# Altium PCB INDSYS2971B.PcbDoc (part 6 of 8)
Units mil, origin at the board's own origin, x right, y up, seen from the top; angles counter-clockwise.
Board outline 6450 x 5820 mil, 6 copper layers (Top Layer, Int1 (PGND), Int2 (AGND), Int3 (Signal), Int4 (PGND), Bottom Layer), stack 70.536 mil thick; 787 components, 431 nets, 2530 pads, 2497 vias.
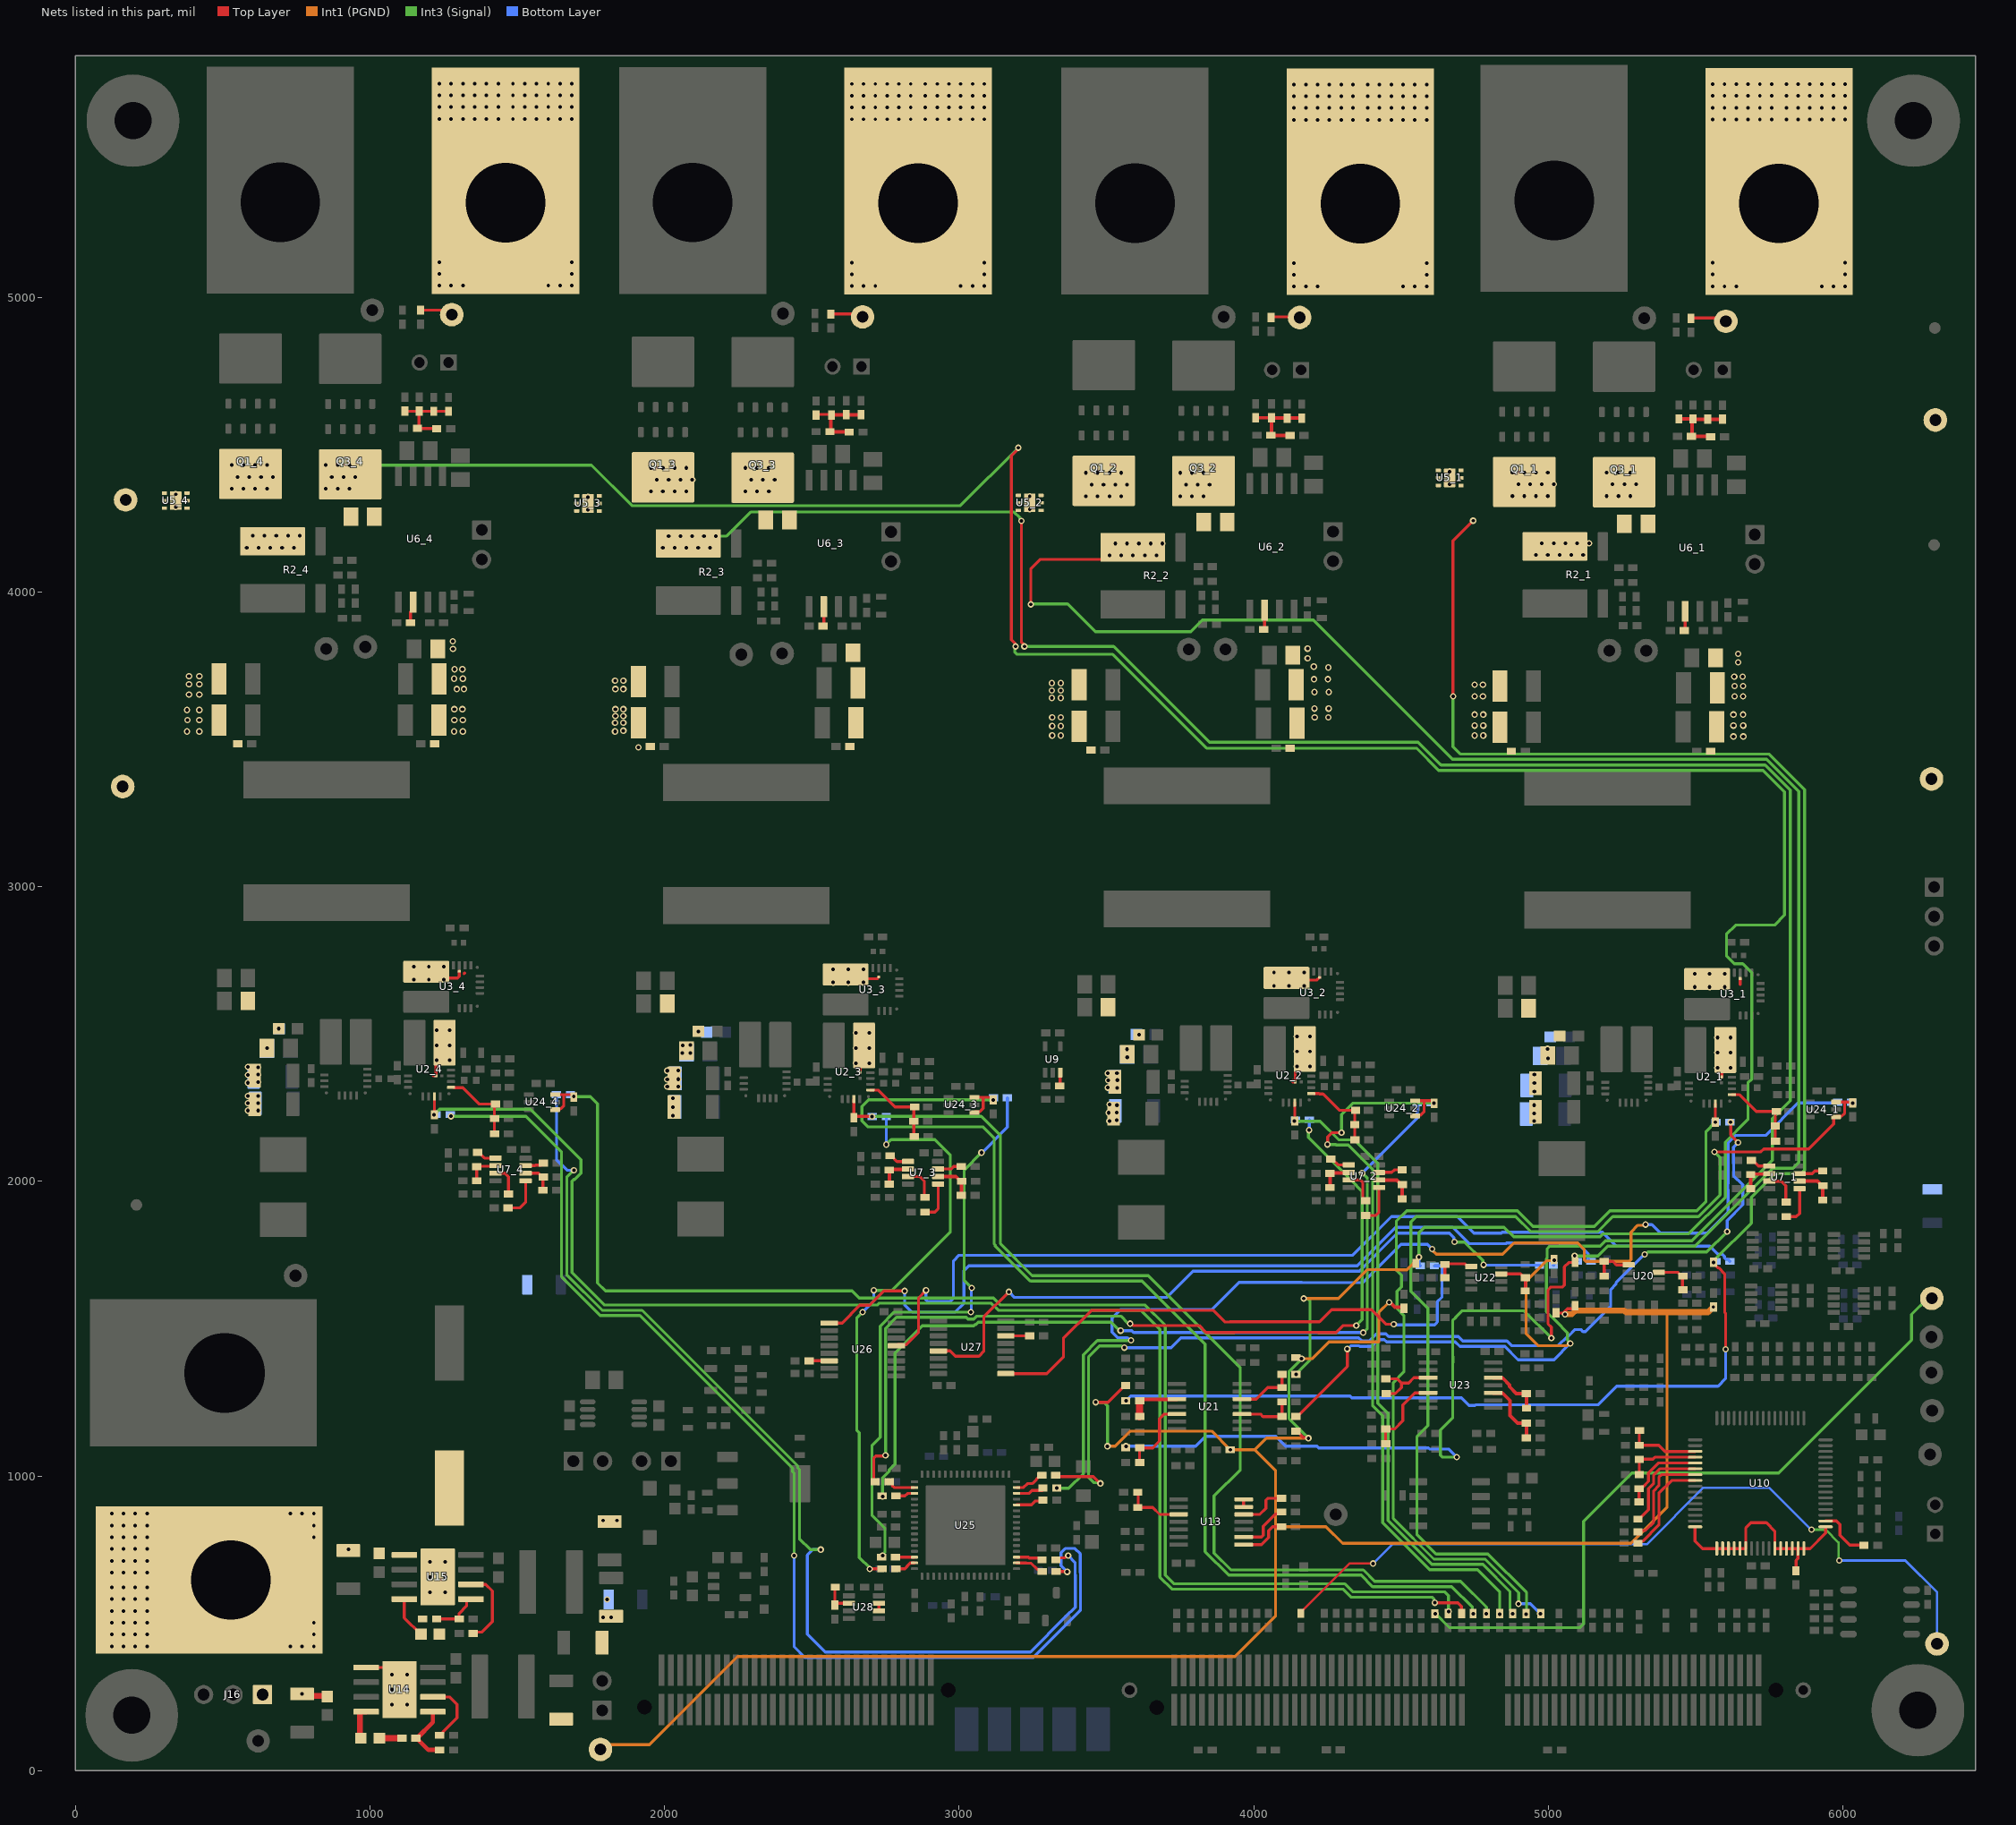
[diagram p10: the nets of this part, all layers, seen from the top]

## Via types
v1: diameter 22, hole 12.5, Top Layer to Bottom Layer, 873 vias
v2: diameter 22, hole 12, Top Layer to Bottom Layer, tented both sides, 788 vias
v3: diameter 22, hole 12, Top Layer to Bottom Layer, 586 vias
v4: diameter 22, hole 12.5, Top Layer to Bottom Layer, tented both sides, 249 vias
v5: diameter 24, hole 12, Top Layer to Bottom Layer, tented both sides, 1 vias

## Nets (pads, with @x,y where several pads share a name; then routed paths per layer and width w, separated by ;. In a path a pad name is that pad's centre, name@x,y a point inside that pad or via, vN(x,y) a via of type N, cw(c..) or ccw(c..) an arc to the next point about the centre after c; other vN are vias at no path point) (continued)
NetR17_1_1: R17_1.1 R18_1.2 R20_1.1 R21_1.2 R25_1.2 R28_1.2 | length 275.9
  Top Layer w12: R20_1.1@5443.39,4587.91 R17_1.1@5493.39,4587.91 ; R28_1.2@5551.1,4527.42 5550.37,4528.15 5486.59,4528.15 R25_1.2@5485.87,4528.88 5488.56,4531.57 5488.56,4584.05 5491.26,4586.75 R21_1.2@5541.26,4586.75 R18_1.2@5591.26,4586.75
NetR17_2_1: R17_2.1 R18_2.2 R20_2.1 R21_2.2 R25_2.2 R28_2.2 | length 275.9
  Top Layer w12: R20_2.1@4010.56,4591.91 R17_2.1@4060.56,4591.91 ; R28_2.2@4123.1,4531.42 4122.37,4532.15 4058.59,4532.15 R25_2.2@4057.87,4532.88 4060.56,4535.57 4060.56,4588.05 4063.26,4590.75 R21_2.2@4113.26,4590.75 R18_2.2@4163.26,4590.75
NetR17_3_1: R17_3.1 R18_3.2 R20_3.1 R21_3.2 R25_3.2 R28_3.2 | length 277.5
  Top Layer w10: R20_3.1@2514.01,4603.52 2560.1,4603.52 R17_3.1@2563.95,4599.66
  Top Layer w12: R28_3.2@2626.49,4543.03 2625.76,4543.76 2561.99,4543.76 R25_3.2@2561.26,4544.48 2563.95,4547.18 2563.95,4599.66 2566.15,4601.86 2566.65,4602.36 R21_3.2@2616.65,4602.36 R18_3.2@2666.65,4602.36
NetR17_4_1: R17_4.1 R18_4.2 R20_4.1 R21_4.2 R25_4.2 R28_4.2 | length 275.9
  Top Layer w10: R20_4.1@1116.26,4613.69 R17_4.1@1166.26,4613.69 ; R28_4.2@1226.1,4554.36 1225.37,4555.09 1161.59,4555.09 R25_4.2@1160.87,4555.81 1166.26,4561.21 R17_4.1@1166.26,4613.69 ; R18_4.2@1266.26,4613.69 R21_4.2@1216.26,4613.69 R17_4.1@1166.26,4613.69
NetR24_1_2: R24_1.2 U7_1.3 | length 82.4
  Top Layer w10: U7_1.3@5853.16,2026.44 5896.45,2026.44 5905.15,2035.14 R24_1.2@5931.98,2035.14
NetR24_2_2: R24_2.2 U7_2.3 | length 82.4
  Top Layer w10: U7_2.3@4425.16,2030.44 4468.45,2030.44 4477.15,2039.14 R24_2.2@4503.98,2039.14
NetR24_3_2: R24_3.2 U7_3.3 | length 82.4
  Top Layer w10: U7_3.3@2928.56,2042.05 2971.84,2042.05 2980.54,2050.75 R24_3.2@3007.37,2050.75
NetR24_4_2: R24_4.2 U7_4.3 | length 63.4
  Top Layer w10: U7_4.3@1528.16,2053.38 1560.36,2053.38 1562.06,2055.08 1581.22,2055.08 R24_4.2@1588.03,2061.89
NetR26_1_2: R26_1.2 U7_1.1 | length 133.5
  Top Layer w10: R26_1.2@5808.27,1880.14 5842.05,1880.14 5853.19,1891.29 U7_1.1@5853.16,1975.26
NetR26_2_2: R26_2.2 U7_2.1 | length 133.5
  Top Layer w10: R26_2.2@4380.27,1884.14 4414.05,1884.14 4425.19,1895.29 U7_2.1@4425.16,1979.26
NetR26_3_2: R26_3.2 U7_3.1 | length 133.5
  Top Layer w10: R26_3.2@2883.66,1895.75 2917.44,1895.75 2928.58,1906.89 U7_3.1@2928.56,1990.87
NetR26_4_2: R26_4.2 U7_4.1 | length 140.3
  Top Layer w10: R26_4.2@1468.62,1910.14 1508.9,1910.14 1528.16,1929.41 U7_4.1@1528.16,2002.2
NetR27_1_2: R27_1.2 R29_1.2 U7_1.2 | length 135.1
  Top Layer w12: U7_1.2@5853.16,2000.85 5913.35,2000.85 5929.05,1985.14 R27_1.2@5932.99,1985.14 5932.49,1984.64 5932.49,1937.26 R29_1.2@5931.98,1936.76
NetR27_2_2: R27_2.2 R29_2.2 U7_2.2 | length 135.1
  Top Layer w12: U7_2.2@4425.16,2004.85 4485.35,2004.85 4501.05,1989.14 R27_2.2@4504.99,1989.14 4504.49,1988.64 4504.49,1941.26 R29_2.2@4503.98,1940.76
NetR27_3_2: R27_3.2 R29_3.2 U7_3.2 | length 135.1
  Top Layer w12: U7_3.2@2928.56,2016.46 2988.74,2016.46 3004.44,2000.75 R27_3.2@3008.38,2000.75 3007.88,2000.25 3007.88,1952.87 R29_3.2@3007.37,1952.37
NetR27_4_2: R27_4.2 R29_4.2 U7_4.2 | length 110.8
  Top Layer w10: U7_4.2@1528.16,2027.79 1571.45,2027.79 1584.09,2015.14 R27_4.2@1588.03,2015.14 1586.38,2013.49 R29_4.2@1586.38,1970.14
NetR30_1_2: R30_1.2 U6_1.2 | length 66.6
  Top Layer w10: R30_1.2@5462.24,3869.5 5465,3872.26 U6_1.2@5465,3934.94
NetR30_2_2: R30_2.2 U6_2.2 | length 66.6
  Top Layer w10: R30_2.2@4034.24,3873.5 4037,3876.26 U6_2.2@4037,3938.94
NetR30_3_2: R30_3.2 U6_3.2 | length 66.6
  Top Layer w10: R30_3.2@2537.64,3885.11 2540.39,3887.87 U6_3.2@2540.39,3950.55
NetR30_4_2: R30_4.2 U6_4.2 | length 73.1
  Top Layer w10: R30_4.2@1137.24,3896.44 1137.24,3933.37 1146.1,3942.22 U6_4.2@1146.1,3965.85
NetR32_1_2: R32_1.2 U7_1.5 | length 68.8
  Top Layer w10: R32_1.2@5690.05,2071.44 5693.99,2071.44 5713.4,2052.03 U7_1.5@5750.8,2052.03
NetR32_2_2: R32_2.2 U7_2.5 | length 68.8
  Top Layer w10: R32_2.2@4262.05,2075.44 4265.99,2075.44 4285.4,2056.03 U7_2.5@4322.8,2056.03
NetR32_3_2: R32_3.2 U7_3.5 | length 68.8
  Top Layer w10: R32_3.2@2765.45,2087.05 2769.38,2087.05 2788.79,2067.64 U7_3.5@2826.19,2067.64
NetR32_4_2: R32_4.2 U7_4.5 | length 68.8
  Top Layer w10: R32_4.2@1365.05,2098.38 1368.99,2098.38 1388.4,2078.97 U7_4.5@1425.8,2078.97
NetR33_1_2: R33_1.2 U7_1.7 | length 117.9
  Top Layer w10: U7_1.7@5750.8,2000.85 5790.65,2000.85 5806.35,1985.14 5806.35,1932.06 R33_1.2@5808.27,1930.14
NetR33_2_2: R33_2.2 U7_2.7 | length 119.9
  Top Layer w10: U7_2.7@4322.8,2004.85 4362.65,2004.85 4370,1997.5 4370,1940.96 4376.81,1934.14 R33_2.2@4380.27,1934.14
NetR33_3_2: R33_3.2 U7_3.7 | length 117.9
  Top Layer w10: U7_3.7@2826.19,2016.46 2866.04,2016.46 2881.75,2000.75 2881.75,1947.67 R33_3.2@2883.66,1945.75
NetR33_4_2: R33_4.2 U7_4.7 | length 107.5
  Top Layer w10: U7_4.7@1425.8,2027.79 1457.73,2027.79 1469.48,2016.05 R33_4.2@1469.48,1957.08
NetR34_1_2: R34_1.2 R35_1.2 U7_1.6 | length 112.6
  Top Layer w12: R35_1.2@5687.2,1975.38 R34_1.2@5687.2,2022.99 5688.93,2024.72 5749.08,2024.72 U7_1.6@5750.8,2026.44
NetR34_2_2: R34_2.2 R35_2.2 U7_2.6 | length 112.6
  Top Layer w12: R35_2.2@4259.2,1979.38 R34_2.2@4259.2,2026.99 4260.93,2028.72 4321.08,2028.72 U7_2.6@4322.8,2030.44
NetR34_3_2: R34_3.2 R35_3.2 U7_3.6 | length 112.6
  Top Layer w12: R35_3.2@2762.59,1990.99 R34_3.2@2762.59,2038.6 2764.32,2040.33 2824.47,2040.33 U7_3.6@2826.19,2042.05
NetR34_4_2: R34_4.2 R35_4.2 U7_4.6 | length 112.5
  Top Layer w10: R35_4.2@1362.2,2002.32 1362.2,2049.72 1364.14,2051.66 1424.08,2051.66 U7_4.6@1425.8,2053.38
NetR77_2: R77.2 U9.3 | length 46.5
  Top Layer w10: R77.2@3341.12,2323.72 3343.09,2325.69 U9.3@3343.09,2369.43
NetR79_1: R79.1 U10.6 | length 323.5
  Top Layer w10: R79.1@5304.57,853.61 5308.5,853.61 5340,885.11 5340,956.69 5357.87,974.56 5357.87,1003.38 5378.85,1024.36 U10.6@5498.54,1024.36
NetR80_1: R80.1 U10.8 | length 345.6
  Top Layer w10: R80.1@5304.57,771.33 5311.38,778.14 5319.79,778.14 5375.58,833.93 5375.58,836.12 5375.75,836.29 5375.75,941.88 5418.78,984.91 5478.94,984.91 5479.02,984.99 U10.8@5498.54,984.99
NetR82_1: R82.1 U10.7 | length 353.1
  Top Layer w10: R82.1@5304.57,810.7 5308.8,814.93 5329.11,814.93 5357.87,843.69 5357.87,949.28 5375.75,967.16 5375.75,995.97 5384.37,1004.59 5498.46,1004.59 U10.7@5498.54,1004.67
NetR99_2: R99.2 U10.34 | length 185.3
  Top Layer w10: U10.34@5941.46,847.19 5977.95,847.19 5990,835.14 5990,798.65 6023.5,765.14 R99.2@6071.38,765.14
NetR101_2: R101.2 U10.16 U10.17 U10.18 U10.19 U10.20 U10.21 U10.22 U10.27 U10.28 U10.29 U10.30 U10.31 U10.32 U10.33 | length 772.2
  Top Layer w10: U10.16@5498.54,827.51 5498.54,779.08 5523.94,753.69 U10.17@5572.36,753.69 U10.18@5592.05,753.69 U10.19@5611.73,753.69 U10.20@5631.42,753.69 U10.21@5651.1,753.69 U10.22@5670.79,753.69 5670.79,824.32 5687.84,841.37 5740.69,841.37 5769.21,812.85 U10.27@5769.21,753.69 U10.28@5788.9,753.69 U10.29@5808.58,753.69 U10.30@5828.27,753.69 U10.31@5847.95,753.69 ; R101.2@5841.02,678.18 5841.02,713.22 5847.87,720.07 5847.87,753.61 U10.31@5847.95,753.69 ; U10.33@5941.46,827.51 5941.46,805.85 5889.29,753.69 U10.32@5867.64,753.69 U10.31@5847.95,753.69
NetR111_1: R111.1 U13.8 | length 167.5
  Top Layer w10: U13.8@3965.94,767.25 4026.47,767.25 4050.51,791.29 4050.51,814.77 4063.66,827.92 R111.1@4094.61,827.92
NetR112_1: R112.1 R114.1 U13.3 | length 192.2
  Top Layer w10: R114.1@3606.06,893.35 R114.1@3611.06,893.35 ; R112.1@3606.06,944.53 3607.87,942.72 3607.87,896.54 3608.56,895.85 R114.1@3611.06,893.35 ; U13.3@3735,870.14 3734.46,869.61 3680.71,869.61 3656.97,893.35 R114.1@3611.06,893.35
NetR113_2: R113.2 U13.9 | length 181.9
  Top Layer w10: U13.9@3965.94,792.84 4026.78,792.84 4032.64,798.69 4032.64,829.17 4074.85,871.38 4087.8,871.38 R113.2@4094.61,878.19
NetR117_1: R117.1 U13.12 | length 167.5
  Top Layer w10: U13.12@3965.94,869.61 4020.75,869.61 4041.49,890.35 4041.49,918.16 4047.35,924.02 R117.1@4094.61,924.02
NetR118_1: R118.1 R122.2 U14.5 | length 210.8
  Top Layer w15: R122.2@1155.12,110.14 R122.2@1159.06,110.14 ; U14.5@1213.19,200.1 1213.19,164.28 R122.2@1159.06,110.14 ; R118.1@1236.38,70.14 1198.13,70.14 1163.37,104.91 1163.37,105.83 R122.2@1159.06,110.14
NetR119_1: R119.1 R123.2 U15.5 | length 169.5
  Top Layer w10: R123.2@1225.87,514.74 R119.1@1302.19,514.74 1305.75,518.29 1305.44,518.29 1302.19,521.55 1302.19,533.4 1327.68,558.89 1327.68,577.23 1332.52,582.07 U15.5@1342.7,582.07
NetR120_1: R120.1 U14.6 | length 223.4
  Top Layer w10: U14.6@1213.19,250.1 1269.43,250.1 1295,224.54 1295,178.77 1247.13,130.89 1247.13,126.96 1240.32,120.14 R120.1@1236.38,120.14
NetR121_1: R121.1 U15.6 | length 270.3
  Top Layer w10: U15.6@1342.7,632.07 1393.02,632.07 1415.28,609.82 1415.28,505.27 1380.18,470.18 1358.06,470.18 1351.28,463.4 R121.1@1349.43,465.25
NetR124_2: R124.2 U14.4 | length 113.2
  Top Layer w20: R124.2@968.5,110.14 965.16,113.49 965.16,199.95 965,199.95 965.16,200.1 U14.4@986.81,200.1
NetR125_2: R125.2 U15.4 | length 142.5
  Top Layer w10: U15.4@1116.32,582.07 1116.32,518.52 1171.44,463.4 R125.2@1172.42,463.4
NetR134_1: R134.1 R135.2 U20.3 | length 134.2
  Top Layer w10: U20.3@5375.58,1691.23 5440.7,1691.23 5455.15,1676.78 R134.1@5455.92,1676.78 ; R135.2@5457.3,1631.78 5455.92,1633.16 R134.1@5455.92,1676.78 ; R134.1@5457.44,1678.44 5455.92,1676.92 R134.1@5455.92,1676.78
NetR137_1: R137.1 R140.2 U21.3 | length 182.9
  Top Layer w12: R140.2@3612.56,1255.52 3617.26,1260.22 3738.6,1260.22 U21.3@3739.49,1261.11
  Top Layer w25: R137.1@3612.56,1201.83 R140.2@3612.56,1255.52
NetR145_1: R145.1 R146.2 U20.5 | length 133.6
  Top Layer w10: R145.1@5189.68,1728.44 R146.2@5189.68,1678.44 5189.68,1678.02 R146.2@5190.92,1676.78 ; R145.1@5196.27,1727.78 5220.43,1727.78 5231.39,1716.82 U20.5@5273.21,1716.82
NetR148_1: R148.1 R152.2 U21.5 | length 268.1
  Top Layer w10: R148.1@3612.56,1045.52 R152.2@3612.56,1095.52 3656.79,1095.52 3680,1118.73 3680,1193.47 3696.46,1209.93 U21.5@3739.49,1209.93
NetR156_1: R156.1 R157.2 U22.3 | length 135.4
  Top Layer w10: U22.3@4840.54,1685.76 4905.39,1685.76 4920.43,1670.72 4920.43,1668.12 4922.12,1668.12 4922.12,1631.43 4923.61,1629.93 4925.43,1628.12 R157.2@4921.8,1628.12
NetR158_1: R158.1 R160.2 U21.10 | length 189.5
  Top Layer w10: U21.10@3959.96,1209.93 4023.35,1209.93 4031.46,1201.83 R160.2@4096.1,1201.83 R158.1@4096.1,1251.83
NetR167_1: R167.1 R169.2 U21.12 | length 193.2
  Top Layer w10: U21.12@3959.96,1261.11 4007.96,1261.11 4046.99,1300.14 R167.1@4096.38,1300.14 4096.38,1338.77 R169.2@4095,1340.14
NetR168_1: R168.1 R170.2 U22.5 | length 137.7
  Top Layer w10: R170.2@4649.05,1673.12 4650.43,1673.12 4649.74,1673.81 4649.05,1674.5 R168.1@4649.05,1718.12 ; R168.1@4651.04,1720.11 4717.61,1720.11 4726.37,1711.35 U22.5@4738.18,1711.35
NetR177_1: R177.1 R179.2 U23.5 | length 276.8
  Top Layer w10: R177.1@4448.07,1109.72 R179.2@4448.07,1159.72 4478.82,1159.72 4506.38,1187.28 4506.38,1241.41 4547.4,1282.43 U23.5@4592.31,1282.43
NetR178_1: R178.1 R180.2 U23.3 | length 232.8
  Top Layer w10: R180.2@4448.07,1329.72 4487.44,1329.72 4501.38,1315.78 ; R178.1@4450,1279.72 4480.75,1279.72 4501.38,1300.35 4501.38,1315.78 ; U23.3@4592.31,1333.61 4543.46,1333.61 4525.63,1315.78 4501.38,1315.78
NetR185_1: R185.1 R187.2 U23.10 | length 235.5
  Top Layer w12: U23.10@4812.79,1282.43 4813.68,1281.54 4844.92,1281.54 4870.24,1256.22 4870.24,1205.04 4895.56,1179.72 R185.1@4925.71,1179.72 R187.2@4925.71,1129.72
NetR186_1: R186.1 R188.2 U23.12 | length 188.5
  Top Layer w12: U23.12@4812.79,1333.61 4813.68,1332.72 4844.92,1332.72 4868.44,1309.2 4868.44,1303.24 4891.96,1279.72 R188.2@4925.71,1279.72 4926.04,1279.38 4926.04,1230.37 R186.1@4926.21,1230.21
NetR208_1: R208.1 U25.46 | length 90.6
  Top Layer w10: U25.46@3194.76,941.2 3237.7,941.2 3246.95,950.45 R208.1@3281.52,950.45
NetR209_1: R209.1 U25.47 | length 102.3
  Top Layer w10: U25.47@3194.76,960.88 3218.61,960.88 3231.85,974.13 3248.03,974.13 3276.06,1002.16 R209.1@3280,1002.16
NetR217_1: R217.1 U25.3 | length 66.4
  Top Layer w10: R217.1@2785.31,932.87 2816.06,932.87 2824.11,940.92 2848.03,940.92 U25.3@2848.31,941.2
NetR219_1: R219.1 U25.2 | length 98.9
  Top Layer w10: R219.1@2761.97,980.57 2765.91,980.57 2772.72,973.76 2772.72,966.74 2778.57,960.88 2807.68,960.88 2808.04,960.53 2827.82,960.53 2828.17,960.88 U25.2@2848.31,960.88
NetR226_1: R226.1 U25.14 | length 64.1
  Top Layer w10: R226.1@2784.18,724.66 U25.14@2848.31,724.66
NetR229_1: R229.1 U25.15 | length 71.9
  Top Layer w10: R229.1@2785.31,685.29 2816.06,685.29 2823.62,692.86 2823.62,694.19 2834.14,704.7 2848.03,704.7 U25.15@2848.31,704.98
NetR232_2: R232.2 U25.44 | length 90.4
  Top Layer w10: U25.44@3194.76,901.83 3245.71,901.83 3259.24,915.35 R232.2@3279.57,915.35
NetR233_1: R233.1 U25.35 | length 90.1
  Top Layer w10: U25.35@3194.76,724.66 3234.63,724.66 3237.4,721.89 3274.67,721.89 R233.1@3281.09,715.48
NetR234_1: R234.1 U25.34 | length 99.5
  Top Layer w10: U25.34@3194.76,704.98 3228.17,704.98 3229.13,704.02 3243.72,704.02 3264.78,682.96 3275.5,682.96 R234.1@3282.31,676.14
NetR236_2: R236.2 U26.13 | length 3272.3
  Top Layer w10: U26.13@2786.82,1442.18 2790.68,1446.04 2820.54,1446.04 2861.97,1487.47 2861.97,1604.54 v2(2887.36,1629.93)
  Bottom Layer w10: v2(2887.36,1629.93) 2887.36,1597.88 2893.22,1592.02 2969.35,1592.02 2980.59,1603.26 2980.59,1730.4 2999.33,1749.14 4336.52,1749.14 4467.53,1880.14 4691.68,1880.14 4747.81,1824.01 4840.72,1824.01 4843.59,1826.88 5184.05,1826.88 5230.79,1780.14 5548.41,1780.14 5575.43,1753.12 5590.5,1753.12 5598.04,1745.58 5598.04,1741.11 5603.9,1735.25 5609.85,1735.25 R236.2@5616.66,1728.44
NetR238_2: R238.2 U26.1 | length 2937
  Top Layer w10: U26.1@2558.48,1518.95 2603.01,1518.95 2632.73,1548.68 2632.73,1550.42 2662.45,1580.14 2696.32,1580.14 2744.42,1628.24 v2(2815.19,1628.24)
  Bottom Layer w10: v2(2815.19,1628.24) 2815.19,1580.08 2839,1556.27 2986.55,1556.27 3016.34,1586.06 3016.34,1697.22 3032.51,1713.39 4351.33,1713.39 4482.33,1844.4 4676.87,1844.4 4733.01,1788.26 4855.53,1788.26 4858.4,1791.14 5036.88,1791.14 5041.72,1786.29 5103.12,1786.29 5136.1,1753.32 5136.1,1735.25 5142.91,1728.44 R238.2@5145.7,1728.44
NetR243_2: R243.2 U26.6 | length 68.4
  Top Layer w10: R243.2@2490.11,1391 U26.6@2558.48,1391
NetR245_2: R245.2 U27.13 | length 2365.2
  Top Layer w10: U27.13@2929.76,1424.35 2969.45,1424.35 2987.67,1406.13 3067.14,1406.13 3083.62,1422.61 3083.62,1539.74 v2(3168.9,1625.02)
  Int3 (Signal) w10: v2(4681.47,1794.26) 4715.12,1794.26 4778.14,1731.23 4778.14,1719.03 v2(4780.43,1716.75)
  Bottom Layer w10: v2(3168.9,1625.02) 3187.71,1606.21 3704.8,1606.21 3794.11,1695.52 4358.73,1695.52 4487.27,1824.06 4664.39,1824.06 4679.18,1809.27 4679.18,1796.56 v2(4681.47,1794.26) ; v2(4780.43,1716.75) 4781.39,1715.78 4969.3,1715.78 R245.2@4970.27,1714.82
NetR247_2: R247.2 U27.1 | length 1871.1
  Top Layer w10: U27.1@3158.11,1347.58 3272.71,1347.58 3297.54,1347.58 3324.54,1374.58 3325.17,1374.58 3351.97,1401.38 3351.97,1402.01 3353.81,1403.85 3353.81,1467.34 3448.47,1562 3863.44,1562 3902.75,1522.69 3918.85,1522.69 3919.85,1523.69 4223.28,1523.69 4261.58,1562 4262.31,1562 4264.98,1564.66 4399.85,1564.66 4449.49,1515.02 v2(4475.61,1515.02)
  Bottom Layer w10: v2(4475.61,1515.02) 4477.91,1512.72 4614.01,1512.72 4619.87,1518.58 4619.87,1519.52 4623.36,1523.01 4623.36,1591.2 4639.21,1607.04 4639.21,1707.54 4633.35,1713.4 R247.2@4613.23,1713.4
NetR250_2: R250.2 R251.1 U28.2 | length 111.7
  Top Layer w10: R251.1@2579.44,622.93 2578.07,621.56 R250.2@2578.07,561.56 2584.33,567.82 U28.2@2625.23,567.82
NetR254_2: R254.2 U27.6 | length 80.8
  Top Layer w10: U27.6@3158.11,1475.53 R254.2@3238.94,1475.53
NetTP18_1: R71.2 TP18.1 | length 2695.3
  Top Layer w8: R71.2@4160,533.77 4160,537.7 4325.19,702.89 v2(4405,702.89)
  Int3 (Signal) w8: v2(5893.46,817.94) 5942.06,817.94 5985.66,774.34 5985.66,715.84 v2(5988.34,713.16)
  Bottom Layer w8: v2(4405,702.89) 4470.55,768.45 5334.26,768.45 5525.96,960.14 5750,960.14 5892.2,817.94 v2(5893.46,817.94) ; v2(5988.34,713.16) 6212.07,713.16 6320,605.23 TP18.1@6320,430.14
NetTP19_1: R54.2 TP19.1 | length 2425
  Top Layer w10: R54.2@4614.73,532.28 4615.39,532.95 v2(4617.06,532.95)
  Int3 (Signal) w10: v2(4617.06,532.95) 4664.97,485.04 5106.55,485.04 5120,498.49 5120,845.74 5284.38,1010.12 5782,1010.12 6233.6,1461.72 6233.6,1548.6 6288.02,1603.02 TP19.1@6302.24,1603.02
NetU13_13: U13.13 U13.14 | length 25.6
  Top Layer w10: U13.13@3965.94,895.2 U13.14@3965.94,920.79
NetU28_6: U28.6 U28.7 | length 25.6
  Top Layer w10: U28.6@2727.59,542.23 U28.7@2727.59,567.82
OS0: R105.1 R110.2 U10.3 | length 248.4
  Top Layer w10: R105.1@5309.76,1154.56 5309.17,1153.97 R110.2@5309.17,1104.56 5375,1104.56 5396.14,1083.41 U10.3@5498.54,1083.41
OS1: R104.1 R109.2 U10.4 | length 244.5
  Top Layer w10: R104.1@5309.17,1004.56 R109.2@5309.17,1056.76 5355,1056.76 5361.96,1063.73 U10.4@5498.54,1063.73
OS2: R103.1 R108.2 U10.5 | length 288.1
  Top Layer w10: R108.2@5308.43,911.8 R103.1@5308.43,956.69 5315.24,963.5 5321.53,963.5 5340,981.96 5340,1010.78 5373.26,1044.04 U10.5@5498.54,1044.04
OUTP1: Q1_1.5 Q1_1.6 Q1_1.7 Q1_1.8 Q1_1.9@4919,4373.95 Q3_1.5 Q3_1.6 Q3_1.7 Q3_1.8 Q3_1.9@5257.36,4372.95 R2_1.3 R6_1.2 R133.1 R140.1 R236.1 U5_1.4 U5_1.5 U5_1.6 | length 6340.6
  Top Layer w10: v2(4676.8,3646.14) 4676.8,4174.26 v2(4745,4242.46) ; v2(5560.92,1725.41) 5560.92,1721.47 5575.6,1706.78 5578.06,1706.78 5599.03,1685.82 5599.03,1556.16 5602.15,1553.04 v2(5602.15,1430.15)
  Int3 (Signal) w10: v2(4676.8,3646.14) 4676.8,3474.8 4701.13,3450.47 5749.12,3450.47 5870,3329.59 5870,2037.91 5858.53,2026.44 5770.23,2026.44 5689.74,1945.95 5689.74,1858.33 5566.92,1735.51 5566.92,1734.65 5560.92,1728.65 v2(5560.92,1725.41)
  Bottom Layer w10: v2(3566.14,1255.52) 3582.13,1271.51 4327.32,1271.51 4333.32,1265.51 4705,1265.51 4731.49,1239.03 4751.26,1239.03 4753.87,1241.64 5168.87,1241.64 5232.09,1304.85 5576.57,1304.85 5602.15,1330.44 v2(5602.15,1430.15)
  other v1: 4958.39,4126.14 4998.39,4126.14 5038.39,4126.14 5078.39,4126.14 5118.39,4126.14 4978.39,4166.14 5018.39,4166.14 5058.39,4166.14 5098.39,4166.14 5138.39,4166.14 4878.39,4326.14 4918.39,4326.14 4958.39,4326.14 4998.39,4326.14 5198.39,4326.14 5238.39,4326.14 5278.39,4326.14 4898.39,4366.14 4938.39,4366.14 4978.39,4366.14 5018.39,4366.14 5218.39,4366.14 5258.39,4366.14 5298.39,4366.14 4878.39,4406.14 4918.39,4406.14 4958.39,4406.14 4998.39,4406.14 5198.39,4406.14 5238.39,4406.14 5278.39,4406.14
OUTP2: Q1_2.5 Q1_2.6 Q1_2.7 Q1_2.8 Q1_2.9@3491,4377.95 Q3_2.5 Q3_2.6 Q3_2.7 Q3_2.8 Q3_2.9@3829.36,4376.95 R2_2.3 R6_2.2 R144.1 R152.1 R238.1 U5_2.4 U5_2.5 U5_2.6 | length 7929.6
  Top Layer w10: v2(3243.39,3958.4) 3243.39,4080.05 3274.32,4110.98 3495.83,4110.98 v1(3510,4125.14) ; v2(5010.51,1468.39) 5010.51,1505.15 4999.14,1516.52 4999.14,1631.69 5008.93,1641.49 5049.14,1641.49 5055,1647.35 5055,1709.73 5069.96,1724.69 R144.1@5090.2,1724.69 ; v2(5089.47,1747.03) 5090.19,1746.3 R144.1@5090.19,1726.13
  Int3 (Signal) w10: v2(3243.39,3958.4) 3245.14,3960.14 3367.94,3960.14 3462.56,3865.52 3786.12,3865.52 3825.51,3904.92 4202.55,3904.92 4674.88,3432.59 5741.72,3432.59 5850.62,3323.69 5850.62,2063.77 5831.17,2044.32 5762.83,2044.32 5498.66,1780.14 5201.46,1780.14 5168.34,1747.03 v2(5089.47,1747.03) ; v2(4689.35,1063.73) 4640.89,1063.73 4634.11,1070.5 4634.11,1155.42 4675.4,1196.71 4675.4,1383.54 4676.8,1384.94 4676.8,1404.72 4675.4,1406.11 4675.4,1527.35 4685.17,1537.12 4685.17,1538.53 4707.11,1560.46 4870.05,1560.46 4870.11,1560.52 4918.37,1560.52 v2(5010.51,1468.39)
  Bottom Layer w10: v2(3566.14,1101.14) 3803.59,1101.14 3836.84,1134.4 4074.94,1134.4 4108.19,1101.14 4214.47,1101.14 4220.47,1095.14 4240.25,1095.14 4593.08,1095.14 4596.82,1091.4 4661.68,1091.4 v2(4689.35,1063.73) ; v2(5089.47,1747.03) 5089.47,1735.25 5096.28,1728.44 R238.1@5098.46,1728.44
  other v1: 3550,4125.14 3590,4125.14 3630,4125.14 3670,4125.14 3530,4165.14 3570,4165.14 3610,4165.14 3650,4165.14 3690,4165.14 3430,4325.14 3470,4325.14 3510,4325.14 3550,4325.14 3750,4325.14 3790,4325.14 3830,4325.14 3450,4365.14 3490,4365.14 3530,4365.14 3570,4365.14 3770,4365.14 3810,4365.14 3850,4365.14 3430,4405.14 3470,4405.14 3510,4405.14 3550,4405.14 3750,4405.14 3790,4405.14 3830,4405.14
OUTP3: Q1_3.5 Q1_3.6 Q1_3.7 Q1_3.8 Q1_3.9@1994.39,4389.56 Q3_3.5 Q3_3.6 Q3_3.7 Q3_3.8 Q3_3.9@2332.75,4388.56 R2_3.3 R6_3.2 R155.1 R160.1 R245.1 U5_3.4 U5_3.5 U5_3.6 | length 8462.3
  Top Layer w10: v2(3211.53,4241.4) 3211.53,3829.38 3219.03,3821.88 3219.03,3817.99 v2(3221.33,3815.69) ; R160.1@4143.35,1201.83 4147.29,1201.83 4317.7,1372.24 v2(4317.7,1431.03)
  Int3 (Signal) w10: v1(2173.78,4190.14) 2210.39,4190.14 2292.22,4271.98 3186.91,4271.98 3206.12,4252.76 3206.12,4250.05 3209.67,4246.51 v2@3212.38,4246.51 ; v2(3221.33,3815.69) 3524.45,3815.69 3850,3490.14 4557.83,3490.14 4633.26,3414.72 4635.28,3414.72 4636.98,3413.02 5736.02,3413.02 5821.4,3327.63 5821.4,2274.06 5761.02,2213.68 5761.02,2071.4 5487.64,1798.02 5193.73,1798.02 5175.86,1780.14 5004.57,1780.14 4996.1,1771.68 4996.1,1739.5 4993.74,1737.14 4993.74,1676.06 4993.66,1675.98 4993.66,1650.08 4994.14,1649.59 4994.14,1623.69 4993.74,1623.29 4993.74,1557.45 5026.68,1524.51 5065.48,1485.71 5065.48,1461.86 5074.52,1452.82 v2(5074.52,1450)
  Int1 (PGND) w10: v2(5019.83,1732.99) 5017.53,1730.69 4993.77,1730.69 4925,1661.93 4925,1482.64 4965.12,1442.52 5063.8,1442.52 5071.28,1450 v2(5074.52,1450)
  Bottom Layer w10: v2(4317.7,1431.03) 4318.32,1431.03 4329.56,1442.27 4357.75,1442.27 4360.13,1439.9 4399.67,1439.9 4422.84,1463.07 4443.25,1463.07 4450.92,1455.4 4684.4,1455.4 4699.9,1439.9 4852.26,1439.9 4897.38,1394.77 5019.3,1394.77 v2(5074.52,1450) ; R245.1@5017.51,1714.82 5019.83,1717.13 v2(5019.83,1732.99)
  other v1: 1993.78,4150.14 2033.78,4150.14 2073.78,4150.14 2113.78,4150.14 2153.78,4150.14 2013.78,4190.14 2053.78,4190.14 2093.78,4190.14 2133.78,4190.14 1953.78,4341.75 1993.78,4341.75 2033.78,4341.75 2073.78,4341.75 2273.78,4341.75 2313.78,4341.75 2353.78,4341.75 1973.78,4381.75 2013.78,4381.75 2053.78,4381.75 2093.78,4381.75 2293.78,4381.75 2333.78,4381.75 2373.78,4381.75 1953.78,4421.75 1993.78,4421.75 2033.78,4421.75 2073.78,4421.75 2273.78,4421.75 2313.78,4421.75 2353.78,4421.75
OUTP4: Q1_4.5 Q1_4.6 Q1_4.7 Q1_4.8 Q1_4.9@594,4400.89 Q3_4.5 Q3_4.6 Q3_4.7 Q3_4.8 Q3_4.9@932.36,4399.89 R2_4.3 R6_4.2 R166.1 R169.1 R247.1 U5_4.4 U5_4.5 U5_4.6 | length 9544.1
  Top Layer w10: v2@3189.16,3826.05 3176.84,3838.37 3176.84,4462.66 3201.08,4486.9 v2(3201.08,4490.14) ; R166.1@4550.43,1721.74 4557.24,1728.56 4557.24,1735.9 4561.01,1739.67 v2(4561.01,1742.91)
  Int3 (Signal) w10: v1(929.77,4431.14) 1751.59,4431.14 1889.23,4293.5 3004.43,4293.5 v2(3201.08,4490.14) ; v2(3191.45,3815.69) 3189.16,3813.4 3189.16,3804.91 3188.84,3804.59 3188.84,3796.31 3196.34,3788.81 3521.34,3788.81 3840,3470.14 4552.55,3470.14 4627.55,3395.14 5728.61,3395.14 5802.2,3321.56 5802.2,2903.74 5768.46,2870 5635.77,2870 5605.06,2839.29 5605.06,2766.07 5632.06,2739.07 5660.12,2739.07 5690.65,2708.54 5690.65,2347.04 5677.94,2334.33 5677.94,2210.01 5601.28,2133.35 5601.28,1946.5 5476.87,1822.09 5186.45,1822.09 5176.09,1811.73 4882.47,1811.73 4849.81,1844.4 4579.6,1844.4 4561.01,1825.8 v2(4561.01,1742.91) ; v2(4143.62,1345.14) 4190.79,1392.31 4190.79,1594.83 4184.93,1600.69 4171.84,1600.69 v2(4170,1602.53)
  Int1 (PGND) w10: v2(4170,1602.53) 4287.49,1602.53 4385.36,1700.4 4482.6,1700.4 4483.1,1699.89 4519.89,1699.89 4561.01,1741.01 v2(4561.01,1742.91)
  Bottom Layer w10: v2(4561.01,1742.91) 4561.01,1718.37 R247.1@4565.99,1713.4
  other v1: 581.33,4151.14 621.33,4151.14 661.33,4151.14 701.33,4151.14 741.33,4151.14 601.33,4191.14 641.33,4191.14 681.33,4191.14 721.33,4191.14 761.33,4191.14 529.77,4351.14 569.77,4351.14 609.77,4351.14 649.77,4351.14 849.77,4351.14 889.77,4351.14 929.77,4351.14 549.77,4391.14 589.77,4391.14 629.77,4391.14 669.77,4391.14 869.77,4391.14 909.77,4391.14 949.77,4391.14 529.77,4431.14 569.77,4431.14 609.77,4431.14 649.77,4431.14 849.77,4431.14 889.77,4431.14
PGND: C1.2 C2_1.1 C2_2.1 C2_3.1 C2_4.1 C3_1.2 C3_2.2 C3_3.2 C3_4.2 C4_1.1 C4_2.1 C4_3.1 C4_4.1 C5_1.2 C5_2.2 C5_3.2 C5_4.2 C6_1.1 C6_2.1 C6_3.1 C6_4.1 C7_1.2 C7_2.2 C7_3.2 C7_4.2 C8_1.2 C8_2.2 C8_3.2 C8_4.2 C9_1.1 C9_2.1 C9_3.1 C9_4.1 C11_1.2 C11_2.2 C11_3.2 C11_4.2 C12_1.2 C12_2.2 C12_3.2 C12_4.2 C13_1.1 C13_2.1 C13_3.1 C13_4.1 C14_1.2 C14_2.2 C14_3.2 C14_4.2 C15_1.2 C15_2.2 C15_3.2 C15_4.2 C16_1.1 C16_2.1 C16_3.1 C16_4.1 C18_1.2 C18_2.2 C18_3.2 C18_4.2 C74.1 C75.1 C76.1 C77.1 C78.1 C79.1 C80.2 C81.2 J2.1 J8_1.1 J8_2.1 J8_3.1 J8_4.1 J16.1 NT1_1.1 NT1_2.1 NT1_3.1 NT1_4.1 NT2_1.1 NT2_2.1 NT2_3.1 NT2_4.1 R6_1.1 R6_2.1 R6_3.1 R6_4.1 R7_1.1 R7_2.1 R7_3.1 R7_4.1 R22_1.1 R22_2.1 R22_3.1 R22_4.1 R122.1 R123.1 R124.1 R125.1 R129.1 R130.2 R132.1 R138.1 R142.1 R149.1 R153.1 R161.1 R163.1 R171.1 R173.1 T2.1 T4_1.1 T4_2.1 T4_3.1 T4_4.1 TP2.1 TP6_1.1 TP6_2.1 TP6_3.1 TP6_4.1 TP12.1 TP13.1 TP14.1 TP23.1 U2_1.6 U2_2.6 U2_3.6 U2_4.6 U3_1.6 U3_2.6 U3_3.6 U3_4.6 U5_1.1 U5_1.2 U5_1.3 U5_1.7@4665.39,4387.69 U5_2.1 U5_2.2 U5_2.3 U5_2.7@3239.46,4303.09 U5_3.1 U5_3.2 U5_3.3 U5_3.7@1740,4301.1 U5_4.1 U5_4.2 U5_4.3 U5_4.7@340,4310.49 U14.1 U14.9 U15.1 U15.9 | length 8749.9
  Top Layer w10: U14.1@986.81,350.1 1050.59,350.1 v2(1074.41,326.29) ; R22_4.1@1171.42,4957.08 1239.97,4957.08 ; 1214.45,2358.96 1214.45,2358.23 NT1_4.1@1223.33,2358.23 1223.33,2408.25 v2(1225.82,2410.74) ; 1240,4957.05 TP6_4.1@1254.49,4957.05 ; v2(1250.61,2684.53) 1256.16,2690.08 1296.92,2690.08 1302.77,2695.93 NT2_4.1@1302.77,2713.35 ; 1318.52,2704.64 1320.57,2706.69 ; R22_3.1@2560.08,4944.34 2642.41,4944.34 TP6_3.1@2643.82,4945.75 ; v2(2649.83,2401.35) 2650.72,2401.35 2663.44,2388.63 NT1_3.1@2663.44,2370.14 ; v2(2674.62,2675.14) 2687.24,2687.76 2721.79,2687.76 2726.79,2692.76 NT2_3.1@2726.79,2693.95 ; TP6_3.1@2682.81,4918.96 TP6_3.1@2682.81,4926.61 ; v2(3463.34,1250.19) 3504.86,1250.19 3561.38,1306.7 R142.1@3565.32,1306.7 ; R22_2.1@4056.69,4932.73 4057.26,4933.31 4058.09,4934.14 TP6_2.1@4140.43,4934.14 ; 4132.27,2342.34 4132.27,2337.34 NT1_2.1@4141.15,2337.34 4141.15,2356.96 4141.21,2357.02 4141.21,2384.5 v2(4146.44,2389.74) ; R163.1@4143.35,1151.83 4147.29,1151.83 4168.42,1130.69 4183.4,1130.69 v2(4185.7,1128.4) ; R171.1@4143.35,1401.83 4145.19,1399.99 4161.02,1399.99 v2(4162.86,1398.15) ; v2(4171.23,2663.53) 4171.23,2670.76 4183.95,2683.47 4214.52,2683.47 NT2_2.1@4223.4,2692.35 ; R161.1@5026.16,1553.33 5050.97,1553.33 v2@5051.58,1553.94 ; v2(5056.67,1548.84) v2@5051.58,1553.94 ; R149.1@5090.92,1578.16 5090.92,1574.23 5084.11,1567.41 5065.05,1567.41 v2@5051.58,1553.94 ; R22_1.1@5484.69,4928.73 5486.09,4930.14 TP6_1.1@5568.43,4930.14 ; R138.1@5560,1574.97 5560,1574.08 v2(5560.46,1573.62) R138.1@5560.92,1573.16 ; 5651.4,2668.98 NT2_1.1@5651.4,2688.35 ; TP6_3.1@2682.81,4926.61 2682.81,4934.26 2690.46,4934.26 TP6_3.1@2682.81,4926.61
  Top Layer w12: v2(4459.9,1589.96) 4462.6,1589.96 4480.19,1572.37 4507.13,1572.37 R173.1@4510,1569.5 ; v4(5574.44,2385.74) 5576.33,2385.74 5588.05,2374.02 NT1_1.1@5588.05,2354.53
  Top Layer w20: C78.1@755,255.1 756.73,253.37 846.77,253.37 C80.2@848.5,251.64 ; R124.1@1031.5,110.14 R122.1@1107.87,110.14
  Int3 (Signal) w10: v2(3463.34,1250.19) 3491.02,1250.19 3503.37,1237.84 v2(3503.37,1101.14) ; v2(4162.86,1398.15) 4119.75,1355.03 4119.75,1194.35 v2(4185.7,1128.4)
  Int1 (PGND) w10: TP23.1@1776.01,88.33 1948.85,88.33 2247.8,387.28 3937.28,387.28 4073.87,523.88 4073.87,827.92 ; v2(3503.37,1101.14) 3529.39,1101.14 3580.51,1152.27 3857.07,1152.27 v2(3920.2,1089.14) 4003.63,1089.14 ; v2(4162.86,1398.15) 4198.29,1398.15 4255.04,1454.9 4424.69,1454.9 4424.69,1554.75 v2(4459.9,1589.96) ; v2(4185.7,1128.4) 4042.88,1128.4 4003.63,1089.14 ; 5403.17,1556.24 5403.17,893.55 5280.95,771.33 4301.92,771.33 4245.33,827.92 4073.87,827.92 ; 4003.63,1089.14 4073.87,1018.9 4073.87,827.92
  Int1 (PGND) w20: v2@5056.67,1549.22 5080.23,1549.22 5093.05,1562.04 5258,1562.04 5263.8,1556.24 5403.17,1556.24 5542.53,1556.24 5559.92,1573.62 v2(5560.46,1573.62)
  other v1: 4665.39,4366.04 4665.39,4409.35
  other v2: 1074.41,223.92 1125.59,223.92 769.1,260.14 1074.41,275.1 1125.59,275.1 1125.59,326.29 1790.8,520.02 1818.39,520.02 1805.08,580.82 1203.92,605.89 1255.1,605.89 1203.92,657.07 1255.1,657.07 1203.92,708.26 1255.1,708.26 926.34,750.97 1790.8,849.01 1838.31,849.01 4191.32,2389.74 2694.72,2401.35 1270.7,2410.74 4146.44,2440.92 4191.32,2440.92 2649.83,2452.53 2694.72,2452.53 1225.82,2461.92 1270.7,2461.92 4146.44,2492.1 4191.32,2492.1 2649.83,2503.71 2694.72,2503.71 1225.82,2513.1 1270.7,2513.1 4068.87,2663.53 4120.05,2663.53 2572.26,2675.14 2623.44,2675.14 1148.25,2684.53 1199.43,2684.53 4068.87,2708.41 4120.05,2708.41 4171.23,2708.41 2572.26,2720.02 2623.44,2720.02 2674.62,2720.02 1148.25,2729.41 1199.43,2729.41 1250.61,2729.41
  other v3: 122.83,421.99 162.83,421.99 202.83,421.99 242.83,421.99 729.1,421.99 769.1,421.99 809.1,421.99 122.83,461.99 162.83,461.99 202.83,461.99 242.83,461.99 809.1,461.99 122.83,501.99 162.83,501.99 202.83,501.99 242.83,501.99 809.1,501.99 122.83,541.99 162.83,541.99 202.83,541.99 242.83,541.99 122.83,581.99 162.83,581.99 202.83,581.99 242.83,581.99 122.83,621.99 162.83,621.99 202.83,621.99 242.83,621.99 122.83,671.99 162.83,671.99 202.83,671.99 242.83,671.99 122.83,711.99 162.83,711.99 202.83,711.99 242.83,711.99 122.83,751.99 162.83,751.99 202.83,751.99 242.83,751.99 122.83,791.99 162.83,791.99 202.83,791.99 242.83,791.99 809.1,791.99 122.83,831.99 162.83,831.99 202.83,831.99 242.83,831.99 809.1,831.99 122.83,871.99 162.83,871.99 202.83,871.99 242.83,871.99 729.1,871.99 769.1,871.99 809.1,871.99 1740,4279.44 3239.46,4281.43 340,4288.83 1740,4322.75 3239.46,4324.74 340,4332.14 4137,5037.08 4177,5037.08 4217,5037.08 4507,5037.08 4547,5037.08 4587,5037.08 5558.43,5038.08 5598.43,5038.08 5638.43,5038.08 5928.43,5038.08 5968.43,5038.08 6008.43,5038.08 2635.39,5038.69 2675.39,5038.69 2715.39,5038.69 3005.39,5038.69 3045.39,5038.69 3085.39,5038.69 1235,5040.02 1275,5040.02 1315,5040.02 1605,5040.02 1645,5040.02 1685,5040.02 4137,5077.08 4587,5077.08 5558.43,5078.08 6008.43,5078.08 2635.39,5078.69 3085.39,5078.69 1235,5080.02 1685,5080.02 4137,5117.08 4587,5117.08 5558.43,5118.08 6008.43,5118.08 2635.39,5118.69 3085.39,5118.69 1235,5120.02 1685,5120.02 4137,5603.35 4177,5603.35 4217,5603.35 4257,5603.35 4297,5603.35 4337,5603.35 4387,5603.35 4427,5603.35 4467,5603.35 4507,5603.35 4547,5603.35 4587,5603.35 5558.43,5604.35 5598.43,5604.35 5638.43,5604.35 5678.43,5604.35 5718.43,5604.35 5758.43,5604.35 5808.43,5604.35 5848.43,5604.35 5888.43,5604.35 5928.43,5604.35 5968.43,5604.35 6008.43,5604.35 2635.39,5604.95 2675.39,5604.95 2715.39,5604.95 2755.39,5604.95 2795.39,5604.95 2835.39,5604.95 2885.39,5604.95 2925.39,5604.95 2965.39,5604.95 3005.39,5604.95 3045.39,5604.95 3085.39,5604.95 1235,5606.28 1275,5606.28 1315,5606.28 1355,5606.28 1395,5606.28 1435,5606.28 1485,5606.28 1525,5606.28 1565,5606.28 1605,5606.28 1645,5606.28 1685,5606.28 4137,5643.35 4177,5643.35 4217,5643.35 4257,5643.35 4297,5643.35 4337,5643.35 4387,5643.35 4427,5643.35 4467,5643.35 4507,5643.35 4547,5643.35 4587,5643.35 5558.43,5644.35 5598.43,5644.35 5638.43,5644.35 5678.43,5644.35 5718.43,5644.35 5758.43,5644.35 5808.43,5644.35 5848.43,5644.35 5888.43,5644.35 5928.43,5644.35 5968.43,5644.35 6008.43,5644.35 2635.39,5644.95 2675.39,5644.95 2715.39,5644.95 2755.39,5644.95 2795.39,5644.95 2835.39,5644.95 2885.39,5644.95 2925.39,5644.95 2965.39,5644.95 3005.39,5644.95 3045.39,5644.95 3085.39,5644.95 1235,5646.28 1275,5646.28 1315,5646.28 1355,5646.28 1395,5646.28 1435,5646.28 1485,5646.28 1525,5646.28 1565,5646.28 1605,5646.28 1645,5646.28 1685,5646.28 4137,5683.35 4177,5683.35 4217,5683.35 4257,5683.35 4297,5683.35 4337,5683.35 4387,5683.35 4427,5683.35 4467,5683.35 4507,5683.35 4547,5683.35 4587,5683.35 5558.43,5684.35 5598.43,5684.35 5638.43,5684.35 5678.43,5684.35 5718.43,5684.35 5758.43,5684.35 5808.43,5684.35 5848.43,5684.35 5888.43,5684.35 5928.43,5684.35 5968.43,5684.35 6008.43,5684.35 2635.39,5684.95 2675.39,5684.95 2715.39,5684.95 2755.39,5684.95 2795.39,5684.95 2835.39,5684.95 2885.39,5684.95 2925.39,5684.95 2965.39,5684.95 3005.39,5684.95 3045.39,5684.95 3085.39,5684.95 1235,5686.28 1275,5686.28 1315,5686.28 1355,5686.28 1395,5686.28 1435,5686.28 1485,5686.28 1525,5686.28 1565,5686.28 1605,5686.28 1645,5686.28 1685,5686.28 4137,5723.35 4177,5723.35 4217,5723.35 4257,5723.35 4297,5723.35 4337,5723.35 4387,5723.35 4427,5723.35 4467,5723.35 4507,5723.35 4547,5723.35 4587,5723.35 5558.43,5724.35 5598.43,5724.35 5638.43,5724.35 5678.43,5724.35 5718.43,5724.35 5758.43,5724.35 5808.43,5724.35 5848.43,5724.35 5888.43,5724.35 5928.43,5724.35 5968.43,5724.35 6008.43,5724.35 2635.39,5724.95 2675.39,5724.95 2715.39,5724.95 2755.39,5724.95 2795.39,5724.95 2835.39,5724.95 2885.39,5724.95 2925.39,5724.95 2965.39,5724.95 3005.39,5724.95 3045.39,5724.95 3085.39,5724.95 1235,5726.28 1275,5726.28 1315,5726.28 1355,5726.28 1395,5726.28 1435,5726.28 1485,5726.28 1525,5726.28 1565,5726.28 1605,5726.28 1645,5726.28 1685,5726.28
  other v4: 3510,2204.42 4952.37,2204.95 3535.03,2207.65 2027.76,2223.36 4952.37,2231 3507.92,2233.01 3535.13,2233.87 585,2240.46 620,2240.46 2027.76,2252.07 3535.63,2258.73 4952.37,2258.77 3511.12,2260.7 585,2265.61 620,2265.12 2027.76,2282.02 585,2290.02 620,2289.68 4952.85,2304.55 3505,2318.13 3536.06,2317.66 2009.01,2321.93 2045.7,2322.1 4952.85,2333.58 585,2334.5 620,2336.93 3505.62,2343.35 3537.07,2343.74 2009.01,2345.68 2045.7,2346.81 585,2361.3 620,2362.28 4952.85,2362.79 3505,2366.79 3535.63,2366.79 2009.01,2375.56 2045.7,2376.01 5619.32,2385.74 620,2387.13 585,2388.6 4999.14,2417.96 3570.42,2421.26 2060.02,2436.01 2086.75,2436.01 5574.44,2436.92 5619.32,2436.92 3570,2448.62 4998.02,2449.78 649.8,2452.5 2061.8,2461.92 2086.75,2462.82 5574.44,2488.1 5619.32,2488.1 3610.8,2497.43 2114.19,2509.04 690.17,2518.43 5496.87,2659.53 5548.05,2659.53 5599.23,2659.53 5496.87,2704.41 5548.05,2704.41 5599.23,2704.41 1911.17,3472.75 5628.76,3510.14 5662.25,3510.14 3315.57,3513.25 3345,3513.25 4750,3513.25 4779.41,3513.25 378.54,3527.16 420.03,3527.16 1284.91,3527.16 1314.98,3527.16 1831.59,3527.16 1860,3529.86 3315.57,3545.11 3345,3545.11 4750,3547.08 4779.41,3547.08 5628.93,3547.08 5661.97,3547.08 1831.59,3556.71 1860,3556.71 380,3566.11 420.03,3566.11 1286.04,3566.11 1314.84,3566.11 3315.57,3575.18 3345,3575.18 4207.1,3575.18 4253.2,3575.18 1832.72,3579.71 1860,3579.71 4750,3584.4 4779.41,3584.4 5628.93,3584.4 5661.24,3584.4 378.25,3600 420.03,3600 1286.04,3602.68 1313.31,3602.68 1832.72,3602.68 1860,3602.68 4206.3,3604.79 4254.36,3604.79 3315,3640.97 3345,3640.97 4750,3646.14 4778,3646.14 5632.5,3646.14 5661.24,3646.14 385.22,3652.34 420.03,3652.34 4206.3,3660.55 4255.14,3660.55 3315,3666.14 3345,3666.14 1294.42,3671.14 1318.52,3671.14 1832.72,3671.14 1860,3671.14 5632.5,3681.11 5661.79,3681.11 4750,3685.64 4778,3686.14 385.22,3687.07 420.03,3687.07 3315,3691.13 3345,3691.13 1831.59,3699.71 1860,3699.71 4204.5,3704.52 4251.69,3704.52 1285.34,3706.11 1314.97,3706.11 5631.56,3713.24 5660,3713.11 385.22,3715 420.03,3715 1286.81,3738.24 1313.48,3738.34 4253.09,3744.26 4203.81,3747.14 5644.71,3761.63 4183.03,3775.06 5644.71,3790.52 1281.51,3807.63 4183.03,3808.23 1280.41,3833.41
PWM_HO1: R11_1.1 R47.1 R199.1 U2_1.14 | length 3171.3
  Top Layer w10: v2(5567.16,2200.95) U2_1.14@5567.16,2263.69
  Int3 (Signal) w10: v2(4898.9,566.42) 4899.76,567.28 4899.76,603.77 4785.83,717.7 4611.79,717.7 4473.66,855.83 4473.66,1317.1 4510,1353.44 4510,1545.12 4486.13,1569 4486.13,1626.63 4501.37,1641.88 4501.37,1681.62 4484.22,1698.77 4484.22,1864.85 4519.51,1900.14 4894.98,1900.14 4947.64,1847.48 5157.06,1847.48 5209.72,1900.14 5504.37,1900.14 5535.65,1931.43 5535.65,2169.45 v2(5567.16,2200.95)
  Bottom Layer w10: v2(4898.9,566.42) 4939.26,566.42 v2(4972.78,532.9)
PWM_HO2: R11_2.1 R51.1 R200.1 U2_2.14 | length 2225.2
  Top Layer w10: R11_2.1@4139.16,2204.95 U2_2.14@4139.16,2267.69
  Int3 (Signal) w10: v2(4137.95,2204.42) 4225.16,2204.42 4288.31,2141.27 4341.32,2141.27 4421.44,2061.15 4421.44,1246.81 4455.79,1212.47 4455.79,848.43 4604.39,699.83 4778.43,699.83 4870.05,608.2 4870.05,544.76 4878.86,535.95 v2(4878.86,532.9)
PWM_HO3: R11_3.1 R48.2 R201.1 U2_3.14 | length 3627.8
  Top Layer w10: U2_3.14@2642.55,2279.3 2642.55,2224.1 2646.32,2220.33 v2(2704.56,2220.33)
  Int3 (Signal) w10: v2@2702.55,2216.56 v2@2704.56,2216.56 ; v2(2704.56,2220.33) 3074.81,2220.33 3140,2155.14 3140,1788.59 3142.13,1786.46 3142.13,1785.78 3247.76,1680.14 3641.99,1680.14 3954.41,1367.72 3954.41,1021.08 3865.54,932.21 3865.54,738.2 3922.54,681.2 4372.02,681.2 4410.97,642.25 4702.9,642.25 4790,555.15 v2(4790,532.9)
PWM_HO4: R11_4.1 R55.2 R202.1 U2_4.14 | length 5051.6
  Top Layer w10: R11_4.1@1218.54,2226.7 U2_4.14@1218.54,2288.69 ; v2(4614.73,569.93) 4693.11,569.93 4705.24,557.79 R55.2@4705.24,533.41
  Int3 (Signal) w10: v2(1217.51,2226.7) 1235.5,2244.69 1544.89,2244.69 1715.76,2073.83 1715.76,2028.1 1694.23,2006.58 1691.61,2006.58 1685.75,2000.72 1685.75,1690.73 1796.07,1580.41 2721.87,1580.41 2727.87,1586.41 3109.37,1586.41 3133.25,1562.54 3616.72,1562.54 3681.51,1497.75 3681.51,656.71 3722.13,616.1 4302.44,616.1 4329.91,588.63 4604.94,588.63 4612.43,581.14 4612.43,572.22 v2(4614.73,569.93)
PWM_LO1: R10_1.1 R49.1 R203.1 U24_1.1 U24_1.3 | length 3515.6
  Top Layer w10: v2(5563.95,2100.14) 5721.38,2100.14 5731.38,2110.14 5884.57,2110.14 5968.88,2194.45 5968.88,2215.45 5971.76,2218.32 U24_1.1@5976.68,2218.32 5979.56,2221.2 5995.63,2221.2 6006.29,2231.86 6006.29,2268.29 6005.07,2269.5 ; U24_1.3@5976.68,2269.5 6005.07,2269.5 ; R10_1.1@6033.46,2269.5 6005.07,2269.5
  Int3 (Signal) w10: v2(4925,530.93) 4926.34,532.27 4926.34,604.01 4794.77,735.57 4619.2,735.57 4554.21,800.56 4554.21,1134.12 4591.25,1171.16 4591.25,1569.3 4533.87,1626.67 4533.87,1862.03 4551.99,1880.14 4889.7,1880.14 4940.24,1829.61 5168.69,1829.61 5219.23,1880.14 5509.65,1880.14 5583.4,1953.9 5583.4,2080.7 v2(5563.95,2100.14)
  other v2: 6033.46,2266.02
PWM_LO2: R10_2.1 R53.1 R204.1 U24_2.1 U24_2.3 | length 2574.7
  Top Layer w10: v2(4250,2125.14) 4250.83,2125.97 4250.83,2151.14 4264.83,2165.14 v2(4298.2,2165.14) ; U24_2.1@4548.68,2222.32 4551.56,2225.2 4567.63,2225.2 4578.29,2235.86 4578.29,2272.29 4577.07,2273.5 ; U24_2.3@4548.68,2273.51 4577.07,2273.5 ; R10_2.1@4605.46,2273.5 4577.07,2273.5
  Int3 (Signal) w10: v2(4250,2125.14) 4278.28,2125.14 4280.02,2123.4 4321.47,2123.4 4403.57,2041.3 4403.57,1239.41 4437.91,1205.06 4437.91,841.02 4596.98,681.95 4760.57,681.95 4835,607.52 v2(4835,530.93) ; v2(4298.2,2165.14) 4298.2,2226.71 4337.28,2265.8 v2(4612.28,2265.8)
PWM_LO3: R10_3.1 R50.2 R205.1 U24_3.1 U24_3.3 | length 4037.9
  Top Layer w10: U24_3.1@3052.08,2233.93 3054.95,2236.81 3071.02,2236.81 3081.68,2247.47 3081.68,2283.9 3080.47,2285.11 ; U24_3.3@3052.08,2285.11 3080.47,2285.11 ; R10_3.1@3108.86,2285.11 3080.47,2285.11
  Int3 (Signal) w10: v2(3115.67,2276.51) 2692.66,2276.51 2670,2253.85 2670,2205.14 2690,2185.14 3080.11,2185.14 3118.89,2146.36 3118.89,1787.04 3122.13,1783.8 3122.13,1780.5 3240.36,1662.27 3243.66,1662.27 3244.04,1661.89 3621.3,1661.89 3835.24,1447.96 3835.24,743.22 3915.13,663.33 4364.61,663.33 4403.57,624.37 4672.49,624.37 4742.7,554.16 4742.7,535.2 v2(4745,532.9)
PWM_LO4: R10_4.1 R56.2 R206.1 U24_4.1 U24_4.3 | length 4718.3
  Top Layer w10: U24_4.1@1628.06,2243.32 1630.94,2246.2 1645.65,2246.2 1647.01,2246.2 1657.67,2256.86 1657.67,2293.29 1656.45,2294.5 ; U24_4.3@1628.06,2294.51 1656.45,2294.5 ; v2(1691.65,2287.69) 1684.84,2294.5 1656.45,2294.5
  Int3 (Signal) w10: v2(1691.65,2287.69) 1747.57,2287.69 1772.13,2263.14 1772.13,1654.91 1798.8,1628.24 2636.76,1628.24 2660.72,1604.28 3116.78,1604.28 3140.65,1580.41 3631.78,1580.41 3700.05,1512.13 3700.05,663.45 3729.53,633.97 4309.84,633.97 4337.31,606.5 4648.64,606.5 4661.33,593.81 v2(4661.33,540.06)
PWMH1: R199.2 R209.2 | length 3478.7
  Top Layer w10: R209.2@3327.24,1002.16 3331.8,997.61 3454.78,997.61 3477.41,974.98 v2(3479.5,974.98) ; v2(5619.32,2200.95) 5619.32,2157.41 5644.19,2132.54 v2(5644.19,2131.97)
  Int3 (Signal) w10: v2(3479.5,974.98) 3477.2,977.27 3468.72,977.27 3468.38,977.61 3456.49,977.61 3439.46,994.64 3439.46,1404.33 3476.66,1441.52 3551.43,1441.52 3557.43,1435.52 v2(3560.67,1435.52) ; v2(5327.06,1752.25) 5330.3,1752.25 5338.2,1760.14 5538.29,1760.14 v2(5607.54,1829.39)
  Bottom Layer w10: v2(3560.67,1435.52) 3719.68,1435.52 3753.23,1469.07 4356.23,1469.07 4367.53,1457.77 4392.27,1457.77 4417.14,1482.64 4448.95,1482.64 4458.32,1473.27 4694.5,1473.27 4710,1457.77 4859.66,1457.77 4874.91,1442.52 5033.28,1442.52 5064.63,1473.88 5067.53,1473.88 5090.67,1497.02 5110.45,1497.02 5117.54,1489.93 5125.83,1489.93 5212.06,1576.15 5212.06,1633.27 5229.93,1651.14 5229.93,1655.12 v2(5327.06,1752.25) ; v2(5607.54,1829.39) 5607.54,1867.36 5660.92,1920.75 5660.92,1988.25 5643.57,2005.6 5643.04,2005.6 5629.47,2019.18 5629.47,2060.86 5628.78,2061.55 5628.78,2115.78 5644.19,2131.19 v2(5644.19,2131.97)
PWMH2: R200.2 R219.2 | length 2994.1
  Top Layer w10: R219.2@2714.73,980.57 2710.35,984.95 2710.35,1061.99 2716.21,1067.85 2747.7,1067.85 v2(2750,1070.14) ; v2(3580.43,1517.24) 3583.67,1517.24 3590.09,1510.82 3814.66,1510.82 3838.53,1486.94 3933.65,1486.94 3934.65,1487.94 4217.65,1487.94 4218.65,1486.94 4280.06,1486.94 4303.93,1510.82 v2(4348.25,1510.82)
  Int3 (Signal) w10: v2(2750,1070.14) 2750,1501.12 2787.28,1538.4 3024.11,1538.4 3030.11,1532.4 3049.89,1532.4 3060.06,1542.56 3548.68,1542.56 3571.71,1519.53 3578.13,1519.53 v2(3580.43,1517.24) ; v2(4188.37,2173.9) 4186.07,2171.61 4186.07,2163.12 4185.7,2162.75 4185.7,2148.99 4349.98,1984.71 4349.98,1983.95 4367.82,1966.12 4367.82,1530.39 v2(4348.25,1510.82)
  Bottom Layer w10: v2(4188.37,2173.9) 4188.37,2207.91 R200.2@4189.07,2208.6
PWMH3: R201.2 R229.2 | length 1973.8
  Top Layer w10: v4(2696.76,684.16) 2697.32,684.73 2737.5,684.73 R229.2@2738.07,685.29
  Int3 (Signal) w10: v4(2672.34,1556.27) 2652.04,1535.97 2652.04,1155.73 2660.77,1147 2660.77,723.39 2696.76,687.4 v4(2696.76,684.16) ; v4(2710.29,1630.14) 2770.97,1630.14 2970,1829.18 2970,2088.9 2917.15,2141.75 2769.07,2141.75 v4(2752.46,2125.14)
  Bottom Layer w10: v4(2672.34,1556.27) 2710.29,1594.21 v4(2710.29,1630.14) ; v4(2752.46,2125.14) R201.2@2752.46,2220.33
PWMH4: R202.2 R234.2 | length 3946.2
  Top Layer w10: R234.2@3329.56,676.14 3365.25,676.14 v2(3366.77,674.62)
  Int3 (Signal) w10: v2(1274.72,2220.82) 1529.07,2220.82 1650,2099.89 1650,1675.93 1781.53,1544.4 1915.93,1544.4 2434,1026.32 2434,1014.18 2440,1008.18 v2(2440,730.14)
  Bottom Layer w10: v2(2440,730.14) 2440,420 2475.68,384.32 3251.61,384.32 3411.2,543.91 3411.2,546.33 3411.87,546.99 3411.87,672.01 3411.2,672.68 3411.2,736.13 3393.31,754.02 3360.11,754.02 3346.13,740.03 3346.13,695.27 v2(3366.77,674.62)
PWML1: R203.2 R208.2 | length 3908
  Int3 (Signal) w10: v2(3331.51,958.85) 3332.14,958.23 3372.09,958.23 3421.59,1007.72 3421.59,1411.73 3469.25,1459.4 3582.61,1459.4 v2(3583.36,1460.14)
  Int1 (PGND) w10: v2(4605.68,1770.39) 4605.68,1767.14 4620.24,1752.59 4845.13,1752.59 4883.68,1791.14 5100.75,1791.14 5122.08,1769.81 5122.08,1734.29 5127.94,1728.44 5229.48,1728.44 5229.54,1728.37 5275.29,1728.37 5281.14,1734.23 5281.14,1827.87 5304.34,1851.07 5328.16,1851.07 v2(5330.34,1853.25)
  Bottom Layer w10: v2(3583.36,1460.14) 3580.43,1460.14 3571.5,1469.07 3538.13,1469.07 3518.85,1488.35 3518.85,1535.95 3547.21,1564.31 3857.34,1564.31 3950.17,1657.14 4162.89,1657.14 4163.41,1656.63 4370.4,1656.63 4499.74,1785.97 4590.1,1785.97 v2(4605.68,1770.39) ; v2(5330.34,1853.25) 5351.79,1853.25 5380.66,1824.39 5539.29,1824.39 5610.2,1895.3 5610.2,1971.44 5609.81,1971.84 5609.81,1991.61 5610.2,1992.01 5610.2,2131.74 5634.57,2156.11 5738.19,2156.11 5848.1,2266.02 5980.4,2266.02 R203.2@5982.67,2268.29
PWML2: R204.2 R217.2 | length 3023
  Int3 (Signal) w10: v2(2740,930.14) 2740,993.38 2762.84,1016.22 2762.84,1020.92 2781.92,1039.99 2781.92,1416.8 2874.92,1509.8 3049.89,1509.8 3054.61,1514.52 3057.29,1514.52 3065.04,1522.27 3515.44,1522.27 3527.91,1509.8 3528.46,1509.8 3544.9,1493.36 v2(3548.14,1493.36) ; v2(4368.35,2028.03) 4385.69,2010.69 4385.69,1500.51 v2(4372.12,1486.94)
  Bottom Layer w10: v2(3548.14,1493.36) 3586.09,1493.36 3592.51,1486.94 v2(4372.12,1486.94) ; v2(4368.35,2028.03) 4554.67,2214.36 R204.2@4554.67,2267.4
PWML3: R205.2 R226.2 | length 1939
  Int3 (Signal) w10: v4(2740,730.14) 2740,733.39 2747.91,741.3 2747.91,823.12 2703.95,867.08 2703.95,1103.14 2732.13,1131.31 2732.13,1508.52 2779.87,1556.27 v4(3040,1556.27) ; v4(3042.36,1638.02) 3042.36,1638.51 3017.22,1663.66 3017.22,2039.13 v4(3075.65,2097.56)
  Bottom Layer w10: v4(3040,1556.27) 3041.18,1557.45 3041.18,1636.84 v4(3042.36,1638.02) ; v4@3076.57,2096.64 3163.62,2183.69 R205.2@3163.62,2283.53
PWML4: R206.2 R233.2 | length 3602.2
  Top Layer w10: R233.2@3328.33,715.48 3335.14,722.29 3358.9,722.29 3366.75,730.14 v2(3370,730.14)
  Int3 (Signal) w10: v2(1691.88,2037.99) 1667.87,2013.98 1667.87,1683.33 1788.93,1562.27 1923.33,1562.27 2451.87,1033.73 2451.87,1028.13 2457.87,1022.13 2457.87,786.8 2494.53,750.14 v2(2530,750.14)
  Bottom Layer w10: R206.2@1632.83,2294.5 1632.83,2073.59 1668.43,2037.99 v2(1691.88,2037.99) ; v2(2530,750.14) 2502.91,750.14 2484.31,731.55 2484.31,463.38 2545.5,402.19 3241.79,402.19 3361.49,521.89 3393.99,554.39 3393.99,664.61 3393.33,665.27 3393.33,706.82 v2(3370,730.14)
PWMLA_1: C28_1.1 D4_1.1 R15_1.2 U2_1.2 | length 276.7
  Top Layer w10: U2_1.2@5623.26,2294.21 5623.34,2294.13 5649.6,2294.13 5706.45,2237.28 D4_1.1@5774.06,2237.28 5770.85,2234.07 R15_1.2@5770.85,2188.29 5770.85,2137.6 C28_1.1@5771.75,2136.71
PWMLA_2: C28_2.1 D4_2.1 R15_2.2 U2_2.2 | length 267.8
  Top Layer w10: U2_2.2@4204.04,2298.13 4221.6,2298.13 4222.77,2296.96 4235.18,2296.96 4290.85,2241.28 D4_2.1@4346.06,2241.28 4342.85,2238.07 R15_2.2@4342.85,2192.29 4342.85,2141.6 C28_2.1@4343.75,2140.71
PWMLA_3: C28_3.1 D4_3.1 R15_3.2 U2_3.2 | length 276.7
  Top Layer w10: U2_3.2@2698.65,2309.81 2698.73,2309.73 2724.99,2309.73 2781.84,2252.89 D4_3.1@2849.45,2252.89 2846.25,2249.68 R15_3.2@2846.25,2203.89 2846.25,2153.21 C28_3.1@2847.14,2152.32
PWMLA_4: C28_4.1 D4_4.1 R15_4.2 U2_4.2 | length 267.8
  Top Layer w10: U2_4.2@1283.42,2319.13 1285.31,2319.13 1286.47,2317.96 1314.78,2317.96 1370.46,2262.28 D4_4.1@1425.44,2262.28 1422.23,2259.07 R15_4.2@1422.23,2213.29 1422.23,2162.6 C28_4.1@1423.13,2161.71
